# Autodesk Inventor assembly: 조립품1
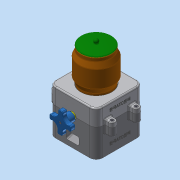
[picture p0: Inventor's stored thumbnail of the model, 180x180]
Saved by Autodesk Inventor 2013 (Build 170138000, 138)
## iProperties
Created: 2018-01
Part Number: 조립품1
Document SubType Name: Assembly
Designer: dgall
Author: dgall
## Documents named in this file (9)
- C:\Users\dgall\Desktop\480107V1020\조립품1.iam
- C:\Users\dgall\Desktop\480107V1020\본체.ipt
- C:\Users\dgall\Desktop\480107V1020\본체커버.ipt
- C:\Users\dgall\Desktop\480107V1020\용기.ipt
- C:\Users\dgall\Desktop\480107V1020\용기캡.ipt
- C:\Users\dgall\Desktop\480107V1020\볼트 M3x12.ipt
- C:\Users\dgall\Desktop\480107V1020\핸들.ipt
- C:\Users\dgall\Desktop\480107V1020\핸들축.ipt
- C:\Users\dgall\Desktop\480107V1020\볼트 M4x12.ipt
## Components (2 placed, 2 different names)
1. 핸들:1
2. 핸들축:1 — 각도:1
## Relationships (1: Angle 1)
- 각도:1 [Angle]: 핸들축:1
